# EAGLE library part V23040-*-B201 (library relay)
SIEMENS Monostabil A0001 = 5V; A0002 = 12V; A0003 = 15V; A0004 = 24V Bistabil C0051 = 5V; C0052 = 12V
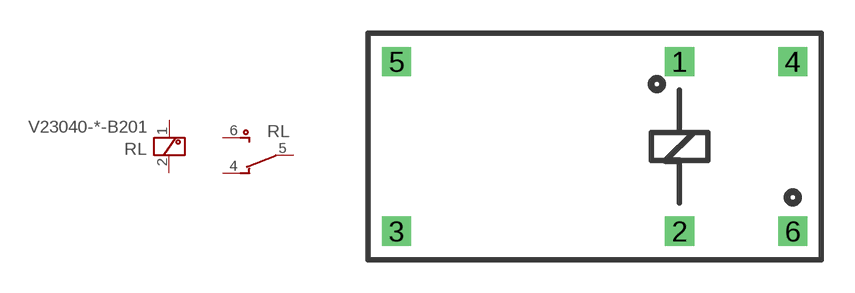
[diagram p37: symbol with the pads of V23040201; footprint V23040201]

Designator prefix RL; gates K=KV K1=UV

## V23040-A0001-B201 (OC_FARNELL: unknown; OC_NEWARK: unknown), V23040-A0002-B201 (MPN: V23040-A0002-B201; OC_FARNELL: 1174994; OC_NEWARK: 24M9075), V23040-A0003-B201 (OC_FARNELL: unknown; OC_NEWARK: unknown), V23040-A0004-B201 (OC_FARNELL: unknown; OC_NEWARK: unknown)  [V23040201]
1  K:1  pas
2  K:2  pas
3  K:3  pas
4  K1:4  pas
5  K1:5  pas
6  K1:6  pas

## Footprint V23040201 (pad centres in mm)
SIEMENS Mono- or Bisatil relay
drill 0.813 pad 1.27 square: 1 3.81,3.81; 2 3.81,-3.81; 3 -8.89,-3.81; 4 8.89,3.81; 5 -8.89,3.81; 6 8.89,-3.81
